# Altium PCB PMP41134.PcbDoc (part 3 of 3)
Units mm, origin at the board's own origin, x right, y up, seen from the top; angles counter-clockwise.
Board outline 252.04 x 132.61 mm, 6 copper layers (Top Layer, Layer 1, Layer 2, Layer 3, Layer 4, Bottom Layer), stack 2.208 mm thick; 221 components, 92 nets, 680 pads, 1197 vias.
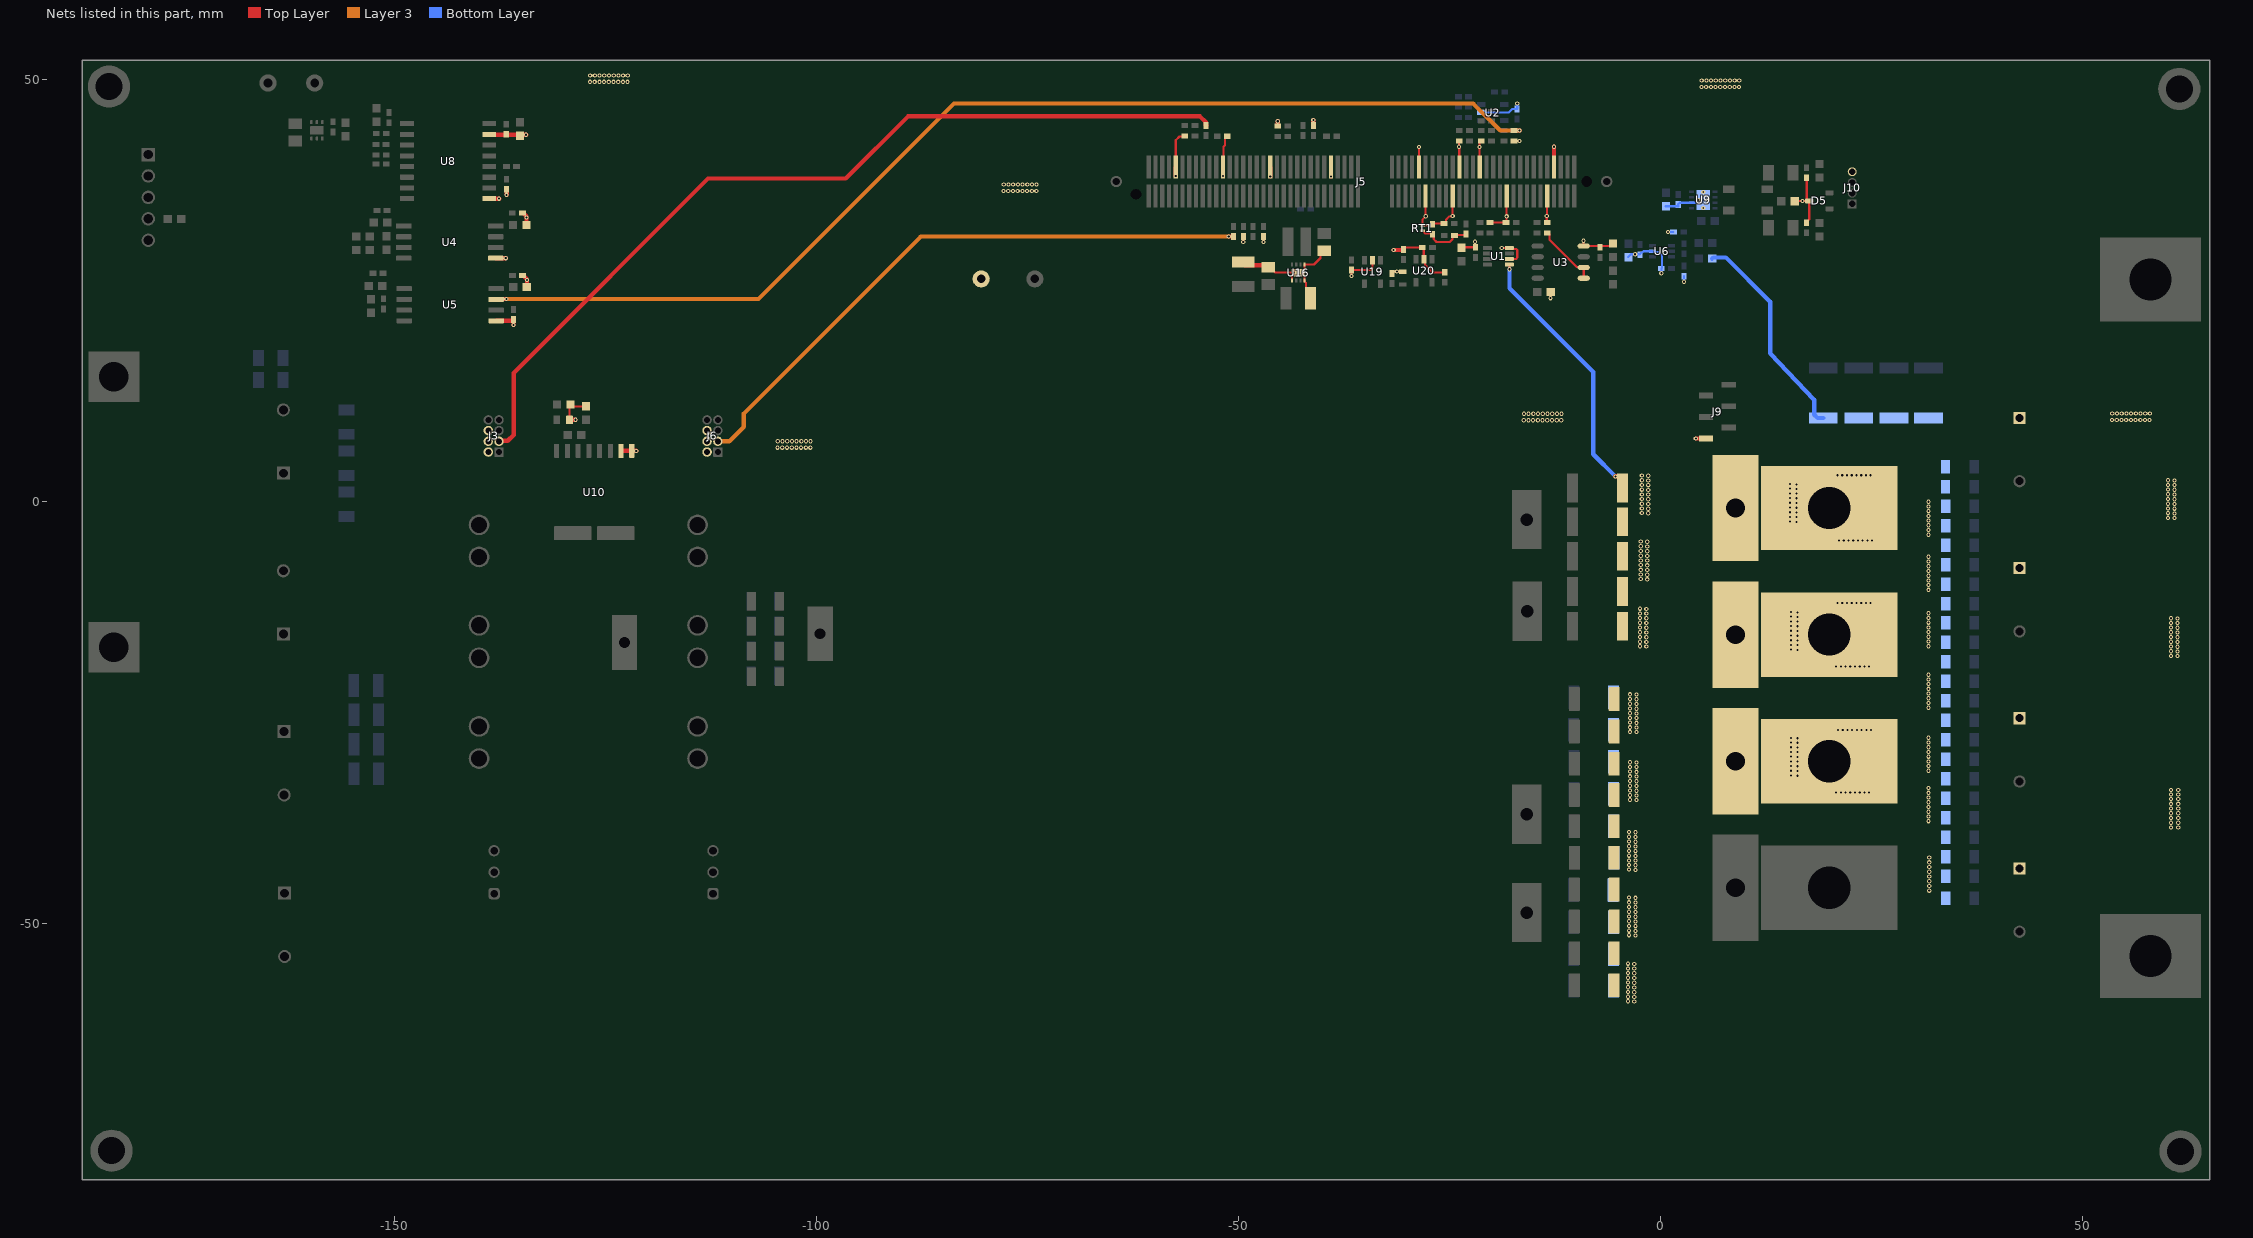
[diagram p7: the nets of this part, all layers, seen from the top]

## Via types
v1: diameter 0.5, hole 0.254, Top Layer to Bottom Layer, tented both sides, 1189 vias
v2: diameter 0.5, hole 0.2, Top Layer to Bottom Layer, 8 vias

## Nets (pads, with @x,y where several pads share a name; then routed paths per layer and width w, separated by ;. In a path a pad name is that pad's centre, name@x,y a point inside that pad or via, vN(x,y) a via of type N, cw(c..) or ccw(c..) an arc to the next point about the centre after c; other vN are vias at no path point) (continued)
SEC_SW1: pad.2@8.839,-15.723 pad.2@19.94,-15.723 R1.2 R2.2 R4.2 R7.2 R16.2 U1.1 | length 32.3
  Top Layer w0.254: U1.1@-17.957,28.113 -17.938,28.094 v1(-17.938,27.567)
  Top Layer w0.508: v1(-5.396,3.023) -4.964,3.023 -4.568,2.627 R1.2@-4.568,1.65
  Bottom Layer w0.508: v1(-17.938,27.567) -17.938,25.304 -8.018,15.384 -8.018,5.645 v1(-5.396,3.023)
  other v1: 20.759,-19.492 21.318,-19.492 21.877,-19.492 22.436,-19.492 22.995,-19.492 23.554,-19.492 24.113,-19.492 24.672,-19.492 16.185,-17.531 15.423,-17.506 -1.727,-17.127 -2.489,-17.094 16.185,-16.972 15.423,-16.947 -1.727,-16.586 -2.489,-16.561 16.185,-16.413 15.423,-16.388 -1.727,-16.027 -2.489,-16.002 16.185,-15.855 15.423,-15.829 -1.727,-15.469 -2.489,-15.443 16.185,-15.296 15.423,-15.27 -1.727,-14.91 -2.489,-14.884 16.185,-14.737 15.423,-14.712 -1.727,-14.351 -2.489,-14.326 16.185,-14.178 15.423,-14.153 -1.727,-13.792 -2.489,-13.767 16.185,-13.619 15.423,-13.594 -1.727,-13.233 -2.489,-13.208 16.185,-13.086 15.423,-13.053 -1.727,-12.675 -2.489,-12.649 20.931,-11.963 21.49,-11.963 22.049,-11.963 22.608,-11.963 23.167,-11.963 23.726,-11.963 24.285,-11.963 24.844,-11.963 -1.626,-9.177 -2.388,-9.144 -1.626,-8.636 -2.388,-8.611 -1.626,-8.077 -2.388,-8.052 -1.626,-7.518 -2.388,-7.493 -1.626,-6.96 -2.388,-6.934 -1.626,-6.401 -2.388,-6.375 -1.626,-5.842 -2.388,-5.817 -1.626,-5.283 -2.388,-5.258 -1.626,-4.724 -2.388,-4.699 -1.499,-1.353 -2.261,-1.321 -1.499,-0.813 -2.261,-0.787 -1.499,-0.254 -2.261,-0.229 -1.499,0.305 -2.261,0.33 -1.499,0.864 -2.261,0.889 -1.499,1.422 -2.261,1.448 -1.499,1.981 -2.261,2.007 -1.499,2.54 -2.261,2.565 -1.499,3.099 -2.261,3.124
SEC_SW2: C5.2 C6.2 C9.2 C10.2 C15.2 C16.2 C19.2 C21.2 C23.2 C27.2 C29.2 C36.2 C37.2 C39.2 C41.2 C43.2 C44.2 C45.2 C46.2 C113.2 pad.2@8.839,-30.723 pad.2@19.94,-30.723
  other v1: -3.15,-59.182 -3.912,-59.149 -3.15,-58.641 -3.912,-58.616 -3.15,-58.082 -3.912,-58.057 -3.15,-57.524 -3.912,-57.498 -3.15,-56.965 -3.912,-56.939 -3.15,-56.406 -3.912,-56.381 -3.15,-55.847 -3.912,-55.822 -3.15,-55.288 -3.912,-55.263 -3.15,-54.73 -3.912,-54.704 -3.023,-51.359 -3.785,-51.326 -3.023,-50.818 -3.785,-50.793 -3.023,-50.259 -3.785,-50.234 -3.023,-49.7 -3.785,-49.675 -3.023,-49.142 -3.785,-49.116 -3.023,-48.583 -3.785,-48.557 -3.023,-48.024 -3.785,-47.999 -3.023,-47.465 -3.785,-47.44 -3.023,-46.906 -3.785,-46.881 -3.023,-43.594 -3.785,-43.561 -3.023,-43.053 -3.785,-43.028 -3.023,-42.494 -3.785,-42.469 -3.023,-41.935 -3.785,-41.91 -3.023,-41.377 -3.785,-41.351 -3.023,-40.818 -3.785,-40.792 -3.023,-40.259 -3.785,-40.234 -3.023,-39.7 -3.785,-39.675 -3.023,-39.141 -3.785,-39.116 -2.906,-35.313 -3.668,-35.281 -2.906,-34.773 -3.668,-34.747 20.759,-34.445 21.318,-34.445 21.877,-34.445 22.436,-34.445 22.995,-34.445 23.554,-34.445 24.113,-34.445 24.672,-34.445 -2.906,-34.214 -3.668,-34.188 -2.906,-33.655 -3.668,-33.63 -2.906,-33.096 -3.668,-33.071 -2.906,-32.537 -3.668,-32.512 16.185,-32.443 15.423,-32.417 -2.906,-31.979 -3.668,-31.953 16.185,-31.884 15.423,-31.858 -2.906,-31.42 -3.668,-31.394 16.185,-31.325 15.423,-31.3 -2.906,-30.861 -3.668,-30.836 16.185,-30.766 15.423,-30.741 16.185,-30.207 15.423,-30.182 16.185,-29.649 15.423,-29.623 16.185,-29.09 15.423,-29.064 16.185,-28.531 15.423,-28.506 16.185,-27.998 15.423,-27.965 -2.906,-27.275 -3.668,-27.243 20.982,-27.01 21.541,-27.01 22.1,-27.01 22.659,-27.01 23.218,-27.01 23.777,-27.01 24.336,-27.01 24.895,-27.01 -2.906,-26.735 -3.668,-26.709 -2.906,-26.176 -3.668,-26.15 -2.906,-25.617 -3.668,-25.592 -2.906,-25.058 -3.668,-25.033 -2.906,-24.499 -3.668,-24.474 -2.906,-23.941 -3.668,-23.915 -2.906,-23.382 -3.668,-23.356 -2.906,-22.823 -3.668,-22.798
SGND: 2.1 C3.2 C18.2 C20.2 C24.2 C26.2 C32.2 C33.2 C34.2 C38.2 C48.2 C49.2 C50.2 C51.2 C52.2 C53.2 C54.2 C55.2 C56.2 C57.2 C58.2 C59.1 C60.2 C61.1 C62.1 C63.1 C64.2 C65.2 C66.2 C67.2 C68.2 C69.2 C70.2 C71.2 C72.2 C74.1 C78.1 C79.2 C80.2 C81.2 C82.2 C83.2 C84.2 C85.2 C87.1 C88.2 C89.2 C92.1 C93.1 C94.2 C95.2 C97.2 C98.2 C99.2 C100.2 C102.2 C103.1 C104.1 C107.2 C108.1 C110.2 C111.2 C112.2 C114.2 C115.2 C116.2 C128.1 C129.1 C130.2 C131.2 C140.1 C142.2 C143.2 C144.2 C149.2 C150.2 C151.2 D5.3 J3.2 J3.4 J3.6 J5.7 J5.10 J5.22 J5.29 J5.35 J5.38 J5.46 J5.47 J5.65 J5.83 J5.97 J5.111 J6.2 J6.4 J6.6 J9.6 J10.4 pad.2@8.839,-0.723 pad.2@19.94,-0.723 R5.1 R6.1 R46.1 R49.1 R50.1 R54.1 R70.1 RT1.1 U1.2 U1.4 U2.2 U3.4 U4.5 U5.5 U6.2 U8.9 U8.15 U9.2 U9.9@5.027,35.764 U10.3 U10.4 U16.1 U16.4 U16.5 U16.9@-42.949,27.169 U19.2 U20.2 | length 158
  Top Layer w0.254: C111.2@-129.293,9.718 -129.293,11.397 C26.2@-129.172,11.518 -128.969,11.316 R6.1@-127.33,11.316 ; J5.111@-57.471,39.648 -57.471,42.837 -57.031,43.277 -56.452,43.277 C89.2@-56.399,43.33 ; J5.97@-51.871,39.648 -51.812,39.706 -51.812,42.059 -51.642,42.229 -51.642,43.145 -51.394,43.393 -51.344,43.393 C88.2@-51.307,43.355 ; C88.2@-51.369,43.318 C88.2@-51.294,43.392 ; v1(-49.471,30.784) C85.2@-49.471,31.434 ; v1(-47.071,30.784) C84.2@-47.071,31.434 ; C130.2@-46.522,27.847 -46.357,27.847 -45.679,27.169 v2(-43.499,27.169) -43.499,26.969 -43.697,26.771 -43.697,26.221 U16.1@-43.699,26.219 ; C128.1@-41.525,24.113 -42.048,24.636 -42.048,25.947 -42.199,26.098 U16.4@-42.199,26.219 -42.201,26.221 -42.201,26.771 -42.399,26.969 v2(-42.399,27.169) -42.399,27.369 -42.201,27.567 -42.201,28.117 U16.5@-42.199,28.119 -41.103,28.119 -40.325,28.896 -40.325,29.323 C131.2@-39.885,29.763 ; v1(-36.652,26.772) -36.662,26.781 -36.662,27.46 C144.2@-36.671,27.469 -34.412,27.469 -34.178,27.704 U19.2@-34.178,28.614 ; C143.2@-31.834,27.069 -31.834,27.13 -31.661,27.303 v1(-31.284,27.303) C142.2@-30.58,27.303 ; C149.2@-30.551,29.832 C149.2@-30.473,29.91 -30.473,29.965 -30.3,30.138 C151.2@-28.271,30.138 -28.259,30.138 -28.086,29.965 U20.2@-28.086,28.748 -27.935,28.597 -27.935,28.098 -27.007,27.17 -26.161,27.17 -26.16,27.169 -25.655,27.169 C150.2@-25.61,27.213 ; J5.47@-28.671,39.648 v1(-28.671,42.052) ; RT1.1@-28.255,32.771 -28.255,32.811 -28.263,32.819 -28.263,33.441 v1(-27.864,33.841) ; RT1.1@-28.225,32.771 -27.203,32.771 C97.2@-27.071,32.902 C97.2@-27.071,33.002 ; v1@-27.871,33.848 -27.867,33.851 -27.867,36.244 J5.46@-27.871,36.248 ; C97.2@-27.007,32.966 -25.611,32.966 -25.438,33.139 -25.438,33.444 -25.054,33.828 -24.718,33.828 v1(-24.671,33.875) J5.38@-24.671,36.248 ; C78.1@-23.883,42.754 -23.917,42.721 v1(-23.917,42.075) -23.894,42.052 -23.894,39.67 J5.35@-23.871,39.648 ; C20.2@-23.442,30.063 -23.344,30.16 -22.011,30.16 v1(-22.011,30.81) ; J5.29@-21.471,39.648 -21.475,39.652 -21.475,42.047 v1(-21.48,42.052) -21.48,42.581 -21.307,42.754 C79.2@-21.283,42.754 ; C81.2@-20.245,33.098 C80.2@-18.346,33.098 -18.271,33.173 J5.22@-18.271,36.248 ; v1(-18.857,30.063) U1.4@-17.957,30.063 -17.859,29.965 -17.174,29.965 -17.026,29.816 -17.026,28.931 -17.174,28.782 -17.938,28.782 U1.2@-17.957,28.763 ; C110.2@-17.397,42.754 v1(-16.747,42.754) ; J5.10@-13.471,36.248 -13.495,36.224 -13.495,33.899 v1(-13.519,33.875) -13.519,33.148 C112.2@-13.469,33.098 ; v1(-13.081,24.133) -13.081,24.839 C3.2@-13.062,24.858 ; v1(-9.171,30.935) -9.171,30.331 U3.4@-9.146,30.306 -5.951,30.306 R5.1@-5.649,30.608 ; C104.1@15.86,35.615 15.907,35.662 D5.3@17.442,35.662 ; C107.2@17.271,33.081 17.271,33.181 17.571,33.481 D5.3@17.571,35.662 D5.3@17.442,35.662 ; C108.1@17.271,38.391 17.271,35.833 D5.3@17.442,35.662
  Top Layer w0.508: U8.9@-138.802,35.921 v1(-137.631,35.921) ; U8.15@-138.802,43.541 -138.756,43.495 -135.3,43.495 C87.1@-135.157,43.351 -135.013,43.495 v1(-134.432,43.495) ; U4.5@-138.028,28.871 v1(-136.849,28.871) ; U5.5@-137.979,21.454 -135.987,21.454 -135.936,21.505 C74.1@-135.936,21.605 v1(-135.936,20.955) ; v1(-136.742,36.374) C94.2@-136.742,37.024 ; C33.2@-134.873,34.226 -134.773,34.226 -134.385,33.838 C32.2@-134.385,32.798 ; C38.2@-134.859,26.796 -134.759,26.796 -134.336,26.373 -134.336,25.5 C48.2@-134.404,25.432 ; C111.2@-129.293,9.718 -129.288,9.723 -128.58,9.723 v1(-128.575,9.728) ; U10.4@-123.19,6.043 v1(-121.387,6.043) ; J5.111@-57.471,39.648 -57.467,39.644 v1(-57.467,38.595) ; J5.97@-51.871,39.648 -51.867,39.644 v1(-51.867,38.608) ; C129.1@-49.471,28.222 -49.284,28.034 -46.71,28.034 C130.2@-46.522,27.847 ; v1(-46.275,38.557) -46.275,39.644 J5.83@-46.271,39.648 ; C83.2@-45.395,44.543 v1(-45.395,45.093) ; C82.2@-41.175,44.593 v1(-41.175,45.243) ; v1(-39.071,38.557) J5.65@-39.071,39.648 ; v1(-31.661,29.832) C149.2@-30.551,29.832 ; J5.7@-12.671,39.648 v1(-12.671,42.075) ; v1(4.14,7.518) 5.313,7.518 J9.6@5.339,7.492
  Bottom Layer w0.254: U2.2@-21.296,46.128 -18.033,46.128 -17.61,46.55 C34.2@-17.026,46.55 v1(-17.026,47.2) ; C93.1@-3.866,29.005 -3.534,29.337 v1(-3.048,29.337) ; v1@-2.998,29.287 -2.948,29.337 -2.514,29.337 C92.1@-2.464,29.287 -2.464,29.387 -2.291,29.56 -2.191,29.56 -2.059,29.692 U6.2@-1.009,29.692 -0.936,29.619 -0.284,29.619 0.116,29.219 0.116,27.702 C98.2@0.053,27.639 v1(0.053,27.089) ; C102.2@0.58,35.015 2.053,35.015 2.053,35.266 2.226,35.439 U9.2@3.627,35.439 4.702,35.439 U9.9@5.027,35.764 ; v1(0.853,31.962) C99.2@1.503,31.962 ; v1(2.738,26.08) C100.2@2.738,26.73
  Bottom Layer w0.508: R70.1@6.062,28.817 6.201,28.956 7.696,28.956 12.954,23.698 12.954,17.602 18.168,12.084 18.168,10.332 18.564,9.936 R46.1@19.218,9.936
  other v1: 31.798,-46.057 31.798,-45.498 31.798,-44.939 31.798,-44.38 31.798,-43.821 31.798,-43.262 31.798,-42.703 31.798,-42.144 60.412,-38.565 61.283,-38.565 60.412,-38.007 61.283,-38.007 31.696,-37.821 60.412,-37.448 61.283,-37.448 31.696,-37.262 60.412,-36.889 61.283,-36.889 31.696,-36.703 60.412,-36.33 61.283,-36.33 31.696,-36.144 60.412,-35.771 61.283,-35.771 31.696,-35.585 60.412,-35.213 61.283,-35.213 31.696,-35.026 60.412,-34.654 61.283,-34.654 31.696,-34.467 60.412,-34.12 61.283,-34.12 31.696,-33.908 31.696,-31.858 31.696,-31.299 31.696,-30.74 31.696,-30.181 31.696,-29.622 31.696,-29.063 31.696,-28.504 31.696,-27.945 31.696,-24.383 31.696,-23.824 31.696,-23.265 31.696,-22.706 31.696,-22.147 31.696,-21.588 31.696,-21.029 31.696,-20.47 61.181,-18.271 60.419,-18.245 61.181,-17.712 60.419,-17.687 61.181,-17.153 60.419,-17.128 31.696,-17.101 61.181,-16.594 60.419,-16.569 31.696,-16.542 61.181,-16.036 60.419,-16.01 31.696,-15.983 61.181,-15.477 60.419,-15.451 31.696,-15.424 61.181,-14.918 60.419,-14.893 31.696,-14.865 61.181,-14.359 60.419,-14.334 31.696,-14.306 61.181,-13.826 60.419,-13.793 31.696,-13.747 31.696,-13.188 31.696,-10.42 31.696,-9.861 31.696,-9.302 31.696,-8.743 31.696,-8.184 31.696,-7.625 31.696,-7.066 31.696,-6.507 21.103,-4.565 21.662,-4.565 22.221,-4.565 22.78,-4.565 23.339,-4.565 23.898,-4.565 24.457,-4.565 25.016,-4.565 31.696,-3.893 31.696,-3.334 31.696,-2.775 16.058,-2.369 15.296,-2.344 31.696,-2.216 60.843,-1.921 60.081,-1.896 16.058,-1.81 15.296,-1.785 31.696,-1.657 60.843,-1.362 60.081,-1.337 16.058,-1.251 15.296,-1.226 31.696,-1.098 60.843,-0.804 60.081,-0.778 16.058,-0.693 15.296,-0.667 31.696,-0.539 60.843,-0.245 60.081,-0.219 16.058,-0.134 15.296,-0.108 31.696,0.02 60.843,0.314 60.081,0.339 16.058,0.425 15.296,0.45 60.843,0.873 60.081,0.898 16.058,0.984 15.296,1.009 60.843,1.432 60.081,1.457 16.058,1.543 15.296,1.568 60.843,1.99 60.081,2.016 16.058,2.076 15.296,2.109 60.843,2.524 60.081,2.556 20.931,3.149 21.49,3.149 22.049,3.149 22.608,3.149 23.167,3.149 23.726,3.149 24.285,3.149 24.844,3.149 -104.647,6.426 -104.088,6.426 -103.529,6.426 -102.97,6.426 -102.412,6.426 -101.853,6.426 -101.294,6.426 -100.761,6.426 -104.621,7.188 -104.063,7.188 -103.504,7.188 -102.945,7.188 -102.386,7.188 -101.827,7.188 -101.269,7.188 -100.728,7.188 -16.256,9.677 -15.697,9.677 -15.138,9.677 -14.58,9.677 -14.021,9.677 -13.462,9.677 -12.903,9.677 -12.344,9.677 -11.811,9.677 53.442,9.703 54,9.703 54.559,9.703 55.118,9.703 55.677,9.703 56.236,9.703 56.794,9.703 57.353,9.703 57.887,9.703 -16.231,10.439 -15.672,10.439 -15.113,10.439 -14.554,10.439 -13.995,10.439 -13.437,10.439 -12.878,10.439 -12.319,10.439 -11.778,10.439 53.467,10.465 54.026,10.465 54.585,10.465 55.143,10.465 55.702,10.465 56.261,10.465 56.82,10.465 57.379,10.465 57.919,10.465 -134.336,26.275 -134.385,33.676 -18.271,33.828 16.762,35.63 -77.876,36.83 -77.318,36.83 -76.759,36.83 -76.2,36.83 -75.641,36.83 -75.082,36.83 -74.524,36.83 -73.99,36.83 -77.851,37.592 -77.292,37.592 -76.733,37.592 -76.175,37.592 -75.616,37.592 -75.057,37.592 -74.498,37.592 -73.958,37.592 4.801,49.149 5.359,49.149 5.918,49.149 6.477,49.149 7.036,49.149 7.595,49.149 8.153,49.149 8.712,49.149 9.246,49.149 -126.873,49.759 -126.314,49.759 -125.755,49.759 -125.197,49.759 -124.638,49.759 -124.079,49.759 -123.52,49.759 -122.961,49.759 -122.428,49.759 4.826,49.911 5.385,49.911 5.944,49.911 6.502,49.911 7.061,49.911 7.62,49.911 8.179,49.911 8.738,49.911 9.278,49.911 -126.848,50.521 -126.289,50.521 -125.73,50.521 -125.171,50.521 -124.612,50.521 -124.054,50.521 -123.495,50.521 -122.936,50.521 -122.395,50.521
  other v2: 5.027,34.814 4.477,35.764 5.577,35.764 5.027,36.714
TMP_SEC: C97.1 R67.2 R89.1 RT1.2 | length 6.6
  Top Layer w0.254: RT1.2@-28.255,32.121 -28.13,32.121 -28.082,32.073 -28.082,31.951 -27.933,31.802 -27.171,31.802 -26.914,31.546 -26.914,31.128 -26.582,30.797 -25.011,30.797 -24.694,31.113 -24.694,31.433 -24.521,31.606 -24.457,31.606 -23.211,31.606 R89.1@-23.086,31.731
Top_ZVD1: J3.3 R101.1 | length 104.7
  Top Layer w0.508: J3.3@-137.643,7.188 -137.595,7.235 -136.605,7.235 -135.906,7.934 -135.906,15.274 -112.878,38.303 -96.571,38.303 -89.205,45.669 -54.597,45.669 -53.919,44.991 -53.919,44.639 R101.1@-53.873,44.593
Top_ZVD2: J6.3 R98.1 | length 72
  Top Layer w0.508: v1(-51.198,31.434) R98.1@-50.648,31.434
  Layer 3 w0.508: J6.3@-111.721,7.188 -110.352,7.188 -108.636,8.905 -108.636,10.465 -87.666,31.434 v1(-51.198,31.434)
VSNS_PRI: R85.2 U5.7 | length 132.8
  Top Layer w0.508: U5.7@-137.979,23.994 -137.945,24.028 v1(-136.774,24.028) ; R85.2@-17.397,43.989 v1(-16.747,43.989)
  Layer 3 w0.508: v1(-136.774,24.028) -106.909,24.028 -83.737,47.2 -22.244,47.2 -19.033,43.989 v1(-16.747,43.989)
VSNS_SEC: R22.2 U3.1 U3.2 | length 7.7
  Top Layer w0.254: R22.2@-13.469,31.851 -13.369,31.851 -13.196,31.678 -13.196,31.043 -9.973,27.82 -9.199,27.82 U3.2@-9.146,27.766 U3.1@-9.146,26.496
pads on no net: J5.1 J5.2 J5.3 J5.4 J5.5 J5.6 J5.8 J5.9 J5.11 J5.12 J5.13 J5.15 J5.16 J5.17 J5.18 J5.19 J5.21 J5.24 J5.26 J5.27 J5.28 J5.32 J5.33 J5.36 J5.37 J5.39 J5.40 J5.41 J5.42 J5.43 J5.44 J5.45 J5.57 J5.58 J5.59 J5.60 J5.61 J5.62 J5.63 J5.64 J5.66 J5.67 J5.74 J5.76 J5.77 J5.78 J5.79 J5.80 J5.81 J5.82 J5.85 J5.87 J5.89 J5.90 J5.91 J5.92 J5.93 J5.94 J5.95 J5.96 J5.99 J5.100 J5.101 J5.102 J5.104 J5.106 J5.107 J5.108 J5.109 J5.110 J5.113 J5.114 J5.115 J5.116 J5.117 J5.118 J5.119 J5.120 J5.181 J5.182 J5.185 J5.186 J7.1 J8.1 J10.3 R26.1 R30.2 R34.1 R74.1 RT1.1S RT1.2S U3.5 U3.6 U3.7 U8.6 U8.7 U8.10 U8.11 U9.5 U9.9@5.027,35.129 U9.9@5.027,36.399 U10.5 U16.8 U16.9@-42.499,27.169 U16.9@-43.399,27.169 U19.4

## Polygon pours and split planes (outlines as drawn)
HV_SW2 on Bottom Layer "BOTTOM_LAYER_HV_SW2_P091" (solid, remove dead copper, pour order 91): -111.347,-11.869 -109.29,-9.812 -107.358,-9.812 -107.096,-10.074 -107.096,-11.869
RTN on Bottom Layer "BOTTOM_LAYER_RTN_P079" (solid, remove dead copper, pour order 79): -186.817,17.712 -186.043,18.486 -165.886,18.486 -165.352,17.952 -165.352,13.464 -166.118,12.956 -175.244,7.214 -185.649,7.214 -186.817,8.382
48Vo- on Bottom Layer "BOTTOM_LAYER_48VO-_P077" (solid, remove dead copper, pour order 77): 33.68,15.088 62.433,15.088 64.008,16.662 64.008,34.163 62.23,35.941 30.173,35.941 16.879,22.648 16.879,15.785 17.577,15.088
48Vo+ on Bottom Layer "BOTTOM_LAYER_48VO+_P075" (solid, remove dead copper, pour order 75): 45.35,-47.964 63.661,-47.964 63.932,-48.235 63.932,-68.732 62.56,-70.104 46.177,-70.104 44.755,-68.682 44.755,-48.569
48Vo+ on Bottom Layer "BOTTOM_LAYER_48VO+_P033" (solid, remove dead copper, pour order 33): 36.986,6.198 43.028,6.198 44.145,5.08 44.185,-3.491 40.386,-5.557 40.386,-9.866 44.182,-12.37 44.146,-21.49 40.107,-24.069 40.107,-28.08 43.869,-30.723 43.869,-39.464 40.107,-41.618 40.107,-45.072 43.869,-47.964 43.869,-68.551 42.24,-70.18 36.246,-70.18 36.246,5.458
48Vo+ on Bottom Layer "BOTTOM_LAYER_48VO+_P036" (solid, remove dead copper, pour order 36): 5.47,-39.716 5.994,-39.192 14.351,-39.192 28.016,-39.192 28.575,-39.751 28.575,-47.276 30.702,-49.403 35.491,-49.403 38.053,-46.841 38.71,-47.498 38.71,-70.18 14.097,-70.18 5.47,-61.554
SGND on Bottom Layer "BOTTOM_LAYER_SGND_P034" (solid, remove dead copper, pour order 34): 16.725,9.157 18.567,7.315 43.663,7.315 45.187,5.791 45.187,-4.242 41.631,-6.214 41.631,-9.093 45.491,-11.963 45.491,-22.018 41.25,-24.961 41.25,-27.305 45.034,-30.124 45.034,-39.962 41.427,-42.329 41.427,-44.554 43.805,-46.431 62.154,-46.431 63.881,-44.704 63.881,10.135 60.884,13.132 18.821,13.132 16.725,11.036
48Vo- on Bottom Layer "BOTTOM_LAYER_48VO-_P040" (solid, remove dead copper, pour order 40): 17.526,19.152 33.147,19.152 33.998,18.301 33.998,15.405 33.68,15.088 17.577,15.088 17.018,15.646 17.018,18.644
3.3Vs on Bottom Layer "BOTTOM_LAYER_3.3VS_P039" (solid, remove dead copper, pour order 39): -33.082,24.384 -32.309,26.187 -30.127,26.187 -29.667,25.727 -29.667,22.885 -30.709,21.844 -133.147,21.844 -137.312,26.01 -137.312,45.263 -136.855,45.72 -133.909,45.72 -133.655,45.466 -133.655,27.381 -130.658,24.384
SEC_SW1 on Bottom Layer "BOTTOM_LAYER_SEC_SW1_P038" (solid, remove dead copper, pour order 38): 12.422,-9.019 28.258,-9.019 28.651,-9.412 28.651,-22.073 28.194,-22.53 11.855,-22.53 11.855,-9.585
SEC_SW2 on Bottom Layer "BOTTOM_LAYER_SEC_SW2_P037" (solid, remove dead copper, pour order 37): 11.527,-24.105 27.822,-24.105 28.575,-24.857 28.575,-36.703 27.813,-37.465 11.527,-37.465
SGND on Bottom Layer "BOTTOM_LAYER_SGND_P035" (solid, remove dead copper, pour order 35): 4.751,5.749 5.149,6.147 11.836,6.147 16.725,11.036 27.877,11.036 37.694,8.56 34.535,5.937 34.611,-47.778 34.326,-48.064 31.096,-48.064 29.921,-46.888 29.921,-8.356 28.652,-7.087 12.408,-7.087 5.994,-7.087 4.751,-5.844
NetR1_1 on Bottom Layer "BOTTOM_LAYER_NETR1_1_P032" (solid, remove dead copper, pour order 32): -20.549,3.123 -19.751,3.921 -9.737,3.921 -9.144,3.327 -9.144,-18.034 -9.728,-18.618 -19.761,-18.618 -20.549,-17.831
SEC_SW1 on Bottom Layer "BOTTOM_LAYER_SEC_SW1_P031" (solid, remove dead copper, pour order 31): -5.618,3.475 -5.173,3.921 1.566,3.921 2.464,3.023 2.464,-6.731 4.751,-9.019 12.422,-9.019 13.056,-9.652 13.056,-21.946 12.471,-22.53 0.102,-22.53 -5.618,-16.81
SEC_SW2 on Bottom Layer "BOTTOM_LAYER_SEC_SW2_P030" (solid, remove dead copper, pour order 30): -6.334,-21.082 -3.48,-21.082 -0.492,-24.069 11.82,-24.069 12.548,-24.797 12.548,-37.109 12.192,-37.465 4.75,-37.465 3.759,-38.456 3.759,-60.325 2.642,-61.443 -5.893,-61.443 -6.655,-60.681 -6.655,-21.415
NetC5_1 on Bottom Layer "BOTTOM_LAYER_NETC5_1_P029" (solid, remove dead copper, pour order 29): -20.879,-21.895 -19.812,-20.828 -9.622,-20.828 -9.144,-21.306 -9.144,-60.452 -10.185,-61.493 -19.558,-61.493 -20.879,-60.173
NetC1_2 on Bottom Layer "BOTTOM_LAYER_NETC1_2_P015" (solid, remove dead copper, pour order 15): -105.131,-10.312 -104.242,-9.423 -97.03,-9.423 -96.241,-10.213 -96.241,-21.717 -96.723,-22.2 -104.724,-22.2 -105.131,-21.793
HV_SW2 on Bottom Layer "BOTTOM_LAYER_HV_SW2_P014" (solid, remove dead copper, pour order 14): -116.314,-11.996 -115.373,-11.055 -107.755,-11.055 -107.096,-11.714 -107.096,-21.69 -107.308,-21.902 -115.831,-21.902 -116.314,-21.419
HVBUS on Bottom Layer "BOTTOM_LAYER_HVBUS_P009" (solid, remove dead copper, pour order 9): -136.931,-0.787 -111.607,-0.787 -110.719,-1.675 -110.719,-7.722 -111.481,-8.484 -137.643,-8.484 -137.643,-1.473 -137.427,-1.257
PGND on Bottom Layer "BOTTOM_LAYER_PGND_P007" (solid, remove dead copper, pour order 7): -136.5,-24.638 -110.719,-24.638 -110.185,-25.171 -110.16,-25.171 -110.16,-34.239 -111.074,-35.154 -140.589,-35.154 -140.589,-28.727
PGND on Bottom Layer "BOTTOM_LAYER_PGND_P002" (solid, remove dead copper, pour order 2): -163.92,13.614 -163.92,18.734 -163.752,18.872 -161.199,18.872 -160.426,18.099 -160.426,10.15 -167.767,4.977 -167.767,-48.717 -165.71,-50.775 -159.69,-50.775 -157.353,-53.111 -157.353,-60.376 -158.217,-61.239 -174.219,-61.239 -176.276,-59.182 -176.276,5.309
PGND on Bottom Layer "BOTTOM_LAYER_PGND_P004" (solid, remove dead copper, pour order 4): -152.641,-32.703 -152.641,-37.752 -159.01,-44.121 -159.01,-49.79 -161.608,-52.388 -161.608,-61.239 -145.068,-61.239 -142.443,-58.615 -142.443,-25.116
PGND on Bottom Layer "BOTTOM_LAYER_PGND_P003" (solid, remove dead copper, pour order 3): -152.641,-20.413 -149.411,-20.413 -145.186,-24.638 -136.5,-24.638 -136.144,-24.994 -136.144,-33.066 -142.727,-39.649 -146.545,-39.649 -152.641,-33.553
HVBUS on Bottom Layer "BOTTOM_LAYER_HVBUS_P001" (solid, remove dead copper, pour order 1): -164.948,-14.619 -150.368,-0.787 -136.931,-0.787 -136.373,-1.346 -136.373,-7.772 -136.754,-8.153 -137.084,-8.484 -143.866,-8.484 -154.211,-18.829 -154.211,-21.388 -164.948,-21.388
HVBUS on Bottom Layer "BOTTOM_LAYER_HVBUS_P000" (solid, remove dead copper, pour order 0): -164.948,-15.367 -163.881,-14.3 -154.686,-14.3 -154.203,-14.783 -154.211,-14.79 -154.211,-33.586 -154.661,-34.036 -158.623,-34.036 -164.948,-28.963
HV_SW2 on Top Layer "TOP_LAYER_HV_SW2_P090" (solid, remove dead copper, pour order 90): -110.312,-10.465 -109.499,-9.652 -107.518,-9.652 -107.096,-10.074 -107.096,-12.536 -107.517,-12.957 -107.876,-12.598 -111.532,-12.598 -111.532,-11.684
48Vo+ on Top Layer "TOP_LAYER_48VO+_P088" (solid, remove dead copper, pour order 88): 43.074,4.318 43.758,3.634 43.758,-1.886 40.107,-5.537 40.107,-9.532 44.145,-12.473 44.145,-20.321 40.107,-23.379 40.107,-28.08 43.805,-31.373 43.805,-37.856 40.107,-41.554 40.107,-45.072 43.869,-48.835 43.869,-67.168 41.085,-69.952 13.792,-69.952 5.47,-61.63 5.47,-39.64 5.994,-39.116 6.071,-39.192 28.016,-39.192 28.651,-39.827 28.651,-49.251 29.312,-49.911 35.268,-49.911 35.917,-49.262 36.115,0.775 40.942,4.318
SGND on Top Layer "TOP_LAYER_SGND_P087" (solid, remove dead copper, pour order 87): 38.35,5.749 43.756,5.749 45.187,4.318 45.187,-2.658 41.25,-6.595 41.25,-8.81 45.491,-11.963 45.491,-21.029 41.25,-24.288 41.25,-27.305 45.034,-30.723 45.034,-38.722 41.427,-42.329 41.427,-44.554 43.304,-46.431 47.372,-46.431 50.362,-43.442 62.451,-43.442 63.881,-42.012 63.881,10.135 61.818,12.198 39.938,12.198
SGND on Top Layer "TOP_LAYER_SGND_P086" (solid, remove dead copper, pour order 86): 11.201,5.749 12.175,5.749 17.268,12.198 43.632,12.198 44.704,11.125 44.704,8.612 34.573,1.251 34.573,-47.462 33.972,-48.064 31.096,-48.064 30.023,-46.99 30.023,-8.686 28.296,-6.96 11.862,-6.96 11.303,-6.401
NetT1_1 on Top Layer "TOP_LAYER_NETT1_1_P084" (solid, remove dead copper, pour order 84): -125.628,-20.295 -119.914,-20.295 -119.736,-20.095 -119.736,-3.607 -120.599,-2.743 -126.009,-2.743 -126.136,-2.87 -126.136,-19.787
RTN on Top Layer "TOP_LAYER_RTN_P080" (solid, remove dead copper, pour order 80): -186.043,18.486 -165.886,18.486 -165.352,17.952 -165.352,13.464 -166.118,12.956 -175.284,7.214 -185.562,7.214 -186.56,8.211 -186.56,17.969
48Vo- on Top Layer "TOP_LAYER_48VO-_P078" (solid, remove dead copper, pour order 78): 16.879,22.648 30.173,35.941 62.23,35.941 64.008,34.163 64.008,16.662 62.433,15.088 17.577,15.088 16.879,15.785
48Vo+ on Top Layer "TOP_LAYER_48VO+_P076" (solid, remove dead copper, pour order 76): 51.41,-46.177 51.765,-45.822 63.83,-45.822 63.932,-45.923 63.932,-68.732 62.56,-70.104 52.476,-70.104 51.41,-69.037
SGND on Top Layer "TOP_LAYER_SGND_P053" (solid, remove dead copper, pour order 53): 4.751,4.953 5.547,5.749 28.889,5.749 29.921,4.717 29.921,-6.563 28.763,-7.721 5.741,-7.721 4.751,-6.732
SEC_SW2 on Top Layer "TOP_LAYER_SEC_SW2_P028" (solid, remove dead copper, pour order 28): -6.655,-22.327 -6.655,-21.415 -6.322,-21.082 -3.505,-21.082 -0.483,-24.105 27.823,-24.105 28.575,-24.857 28.575,-36.897 28.007,-37.465 4.75,-37.465 3.759,-38.456 3.759,-60.35 2.667,-61.443 -5.893,-61.443 -6.655,-60.681
NetC5_1 on Top Layer "TOP_LAYER_NETC5_1_P027" (solid, remove dead copper, pour order 27): -20.879,-21.895 -19.812,-20.828 -9.622,-20.828 -9.144,-21.306 -9.144,-60.452 -10.185,-61.493 -19.558,-61.493 -20.879,-60.173
SEC_SW1 on Top Layer "TOP_LAYER_SEC_SW1_P026" (solid, remove dead copper, pour order 26): -5.618,3.475 -5.173,3.921 1.566,3.921 2.464,3.023 2.464,-6.731 4.751,-9.019 27.306,-9.019 28.538,-10.25 28.538,-21.338 27.346,-22.53 0.102,-22.53 -5.618,-16.81
NetR1_1 on Top Layer "TOP_LAYER_NETR1_1_P025" (solid, remove dead copper, pour order 25): -20.549,3.123 -19.751,3.921 -9.737,3.921 -9.144,3.327 -9.144,-18.034 -9.728,-18.618 -19.761,-18.618 -20.549,-17.831
NetC1_2 on Top Layer "TOP_LAYER_NETC1_2_P013" (solid, remove dead copper, pour order 13): -105.131,-10.293 -104.49,-9.652 -96.801,-9.652 -96.241,-10.213 -96.241,-21.717 -96.977,-22.454 -104.394,-22.454 -105.131,-21.717
HV_SW2 on Top Layer "TOP_LAYER_HV_SW2_P012" (solid, remove dead copper, pour order 12): -115.494,-21.971 -107.267,-21.971 -107.096,-21.793 -107.096,-11.446 -107.487,-11.055 -115.475,-11.055 -115.976,-11.556 -115.976,-21.488
HV_SW1 on Top Layer "TOP_LAYER_HV_SW1_P010" (solid, remove dead copper, pour order 10): -141.732,-12.598 -134.49,-12.598 -132.258,-10.269 -132.258,-3.404 -131.653,-2.798 -126.656,-2.798 -126.598,-2.856 -126.598,-17.607 -129.468,-20.477 -141.626,-20.477 -142.291,-19.812 -142.291,-13.157
PGND on Top Layer "TOP_LAYER_PGND_P008" (solid, remove dead copper, pour order 8): -137.427,-24.638 -110.719,-24.638 -110.16,-25.197 -110.16,-34.239 -111.074,-35.154 -140.589,-35.154 -140.589,-24.847
PGND on Top Layer "TOP_LAYER_PGND_P006" (solid, remove dead copper, pour order 6): -164.354,13.322 -161.179,13.322 -160.813,12.956 -160.813,9.878 -167.767,4.977 -167.767,-48.743 -165.557,-50.952 -165.506,-50.902 -160.045,-50.902 -160.045,-50.825 -159.01,-49.79 -159.01,-44.121 -152.641,-37.752 -152.641,-20.413 -149.411,-20.413 -145.186,-24.638 -136.5,-24.638 -136.144,-24.994 -136.144,-33.122 -142.443,-39.421 -142.443,-58.615 -145.068,-61.239 -174.219,-61.239 -176.276,-59.182 -176.276,5.309
HVBUS on Top Layer "TOP_LAYER_HVBUS_P005" (solid, remove dead copper, pour order 5): -164.948,-14.619 -150.368,-0.787 -136.931,-0.787 -136.373,-1.346 -136.373,-7.772 -137.084,-8.484 -143.942,-8.484 -155.143,-19.685 -155.143,-33.553 -155.626,-34.036 -158.623,-34.036 -164.948,-28.963
NetC1_2 on Layer 2 "LAYER_2_NETC1_2_P093" (solid, remove dead copper, pour order 93): -105.131,-10.312 -104.555,-9.737 -96.716,-9.737 -96.241,-10.213 -96.241,-21.717 -96.977,-22.454 -104.47,-22.454 -105.131,-21.793
HV_SW2 on Layer 2 "LAYER_2_HV_SW2_P092" (solid, remove dead copper, pour order 92): -116.314,-10.316 -115.942,-9.944 -107.425,-9.944 -106.941,-10.428 -106.941,-21.946 -107.449,-22.454 -115.716,-22.454 -116.314,-21.856
48Vo+ on Layer 2 "LAYER_2_48VO+_P089" (solid, remove dead copper, pour order 89): 5.98,-39.154 33.147,-39.154 34.273,-38.029 34.273,3.878 36.144,5.749 55.241,5.749 56.642,4.348 56.642,-40.616 49.632,-47.626 49.632,-60.195 47.216,-62.611 6.783,-62.611 5.47,-61.299 5.47,-39.827
SEC_SW1 on Layer 2 "LAYER_2_SEC_SW1_P068" (solid, remove dead copper, pour order 68): -5.695,3.399 -5.173,3.921 1.566,3.921 2.464,3.023 2.464,-6.731 4.751,-9.019 27.864,-9.019 28.538,-9.692 28.538,-22.186 28.194,-22.53 0.102,-22.53 -5.699,-16.73
SEC_SW2 on Layer 2 "LAYER_2_SEC_SW2_P071" (solid, remove dead copper, pour order 71): -6.655,-21.415 -6.322,-21.082 -3.505,-21.082 -0.518,-24.069 27.808,-24.069 28.575,-24.836 28.575,-36.897 28.007,-37.465 4.75,-37.465 3.759,-38.456 3.759,-60.325 2.642,-61.443 -5.893,-61.443 -6.655,-60.681
NetC5_1 on Layer 2 "LAYER_2_NETC5_1_P070" (solid, remove dead copper, pour order 70): -20.879,-21.895 -19.812,-20.828 -9.622,-20.828 -9.144,-21.306 -9.144,-60.452 -10.185,-61.493 -19.558,-61.493 -20.879,-60.173
NetR1_1 on Layer 2 "LAYER_2_NETR1_1_P069" (solid, remove dead copper, pour order 69): -20.549,3.123 -19.751,3.921 -9.737,3.921 -9.144,3.327 -9.144,-18.034 -9.728,-18.618 -19.761,-18.618 -20.549,-17.831 -20.549,3.123
HV_SW1 on Layer 2 "LAYER_2_HV_SW1_P067" (solid, remove dead copper, pour order 67): -132.258,-3.404 -131.572,-2.718 -126.737,-2.718 -126.598,-2.856 -126.598,-17.607 -129.468,-20.477 -141.626,-20.477 -142.291,-19.812 -142.291,-13.157 -141.732,-12.598 -134.49,-12.598 -132.258,-10.367
NetT1_1 on Layer 2 "LAYER_2_NETT1_1_P066" (solid, remove dead copper, pour order 66): -126.136,-2.87 -126.031,-2.765 -120.577,-2.765 -119.736,-3.607 -119.736,-19.966 -120.062,-20.293 -125.734,-20.293 -126.136,-19.89
SGND on Layer 2 "LAYER_2_SGND_P055" (solid, remove dead copper, pour order 55): -139.236,4.623 -96.54,4.623 -95.391,5.712 -95.391,20.244 -21.445,20.244 -21.445,7.876 -20.319,6.68 34.822,6.68 39.853,11.711 39.853,50.063 38.049,51.867 -138.659,51.867 -139.903,50.623 -139.903,5.29
SGND on Layer 2 "LAYER_2_SGND_P051" (solid, remove dead copper, pour order 51): 4.751,4.953 5.547,5.749 29.098,5.749 30.226,4.621 30.226,-6.647 29.152,-7.721 5.741,-7.721 4.751,-6.732
12Vp on Layer 2 "LAYER_2_12VP_P021" (solid, remove dead copper, pour order 21): -166.802,51.689 -163.151,51.689 -162.814,51.352 -162.814,47.574 -160.477,45.237 -160.477,42.723 -161.087,42.113 -161.188,42.215 -164.948,42.215 -164.948,43.485 -167.284,45.822 -167.284,51.206
12Vp on Layer 2 "LAYER_2_12VP_P019" (solid, remove dead copper, pour order 19): -114.732,-38.049 -110.439,-38.049 -109.804,-38.684 -109.804,-41.935 -110.315,-42.446 -143.457,-42.446 -148.67,-37.233 -148.67,9.335 -164.948,25.612 -164.948,43.201 -164.608,43.541 -160.879,43.541 -160.477,43.139 -160.477,27.124 -144.636,11.283 -144.636,-35.018 -141.605,-38.049
HVBUS on Layer 4 "LAYER_4_HVBUS_P095" (solid, remove dead copper, pour order 95): -186.817,-13.668 -186.357,-13.208 -155.321,-13.208 -154.229,-14.3 -154.229,-33.604 -154.661,-34.036 -158.623,-34.036 -163.719,-29.947 -186.614,-29.947 -186.817,-29.743
SGND on Layer 4 "LAYER_4_SGND_P044" (solid, remove dead copper, pour order 44): -21.464,20.244 -21.464,7.851 -20.206,6.593 29.647,6.68 32.69,3.637 32.69,-43.924 34.587,-45.822 48.285,-45.822 49.936,-44.171 49.936,48.235 46.304,51.867 -138.659,51.867 -139.903,50.623 -139.903,5.29 -139.236,4.623 -96.578,4.623 -95.391,5.712 -95.391,20.244
NetC5_1 on Layer 4 "LAYER_4_NETC5_1_P064" (solid, remove dead copper, pour order 64): -20.879,-21.895 -19.812,-20.828 -9.622,-20.828 -9.144,-21.306 -9.144,-60.452 -10.185,-61.493 -19.558,-61.493 -20.879,-60.173
NetR1_1 on Layer 4 "LAYER_4_NETR1_1_P063" (solid, remove dead copper, pour order 63): -20.549,3.123 -19.751,3.921 -9.737,3.921 -9.144,3.327 -9.144,-18.034 -9.728,-18.618 -19.761,-18.618 -20.549,-17.831 -20.549,3.123
48Vo+ on Layer 4 "LAYER_4_48VO+_P062" (solid, remove dead copper, pour order 62): 5.47,-39.673 5.951,-39.192 28.81,-39.192 29.921,-40.303 29.921,-61.216 28.552,-62.586 6.541,-62.586 5.47,-61.515
SEC_SW2 on Layer 4 "LAYER_4_SEC_SW2_P061" (solid, remove dead copper, pour order 61): -6.655,-22.276 -6.655,-21.415 -6.322,-21.082 -3.505,-21.082 -0.518,-24.069 28.9,-24.069 29.921,-25.091 29.921,-36.662 29.118,-37.465 4.75,-37.465 3.759,-38.456 3.759,-60.325 2.642,-61.443 -5.893,-61.443 -6.655,-60.681
SEC_SW1 on Layer 4 "LAYER_4_SEC_SW1_P060" (solid, remove dead copper, pour order 60): -5.173,3.921 1.566,3.921 2.464,3.023 2.464,-6.731 4.751,-9.019 28.931,-9.019 29.921,-10.008 29.921,-21.812 29.204,-22.53 0.102,-22.53 -5.623,-16.806 -5.623,3.471
SGND on Layer 4 "LAYER_4_SGND_P052" (solid, remove dead copper, pour order 52): 4.751,4.953 5.547,5.749 28.603,5.749 29.921,4.431 29.921,-6.563 28.763,-7.721 5.741,-7.721 4.751,-6.732
PGND on Layer 4 "LAYER_4_PGND_P023" (solid, remove dead copper, pour order 23): -186.157,42.871 -176.221,51.689 -147.65,51.689 -146.837,50.876 -146.837,16.525 -143.65,12.648 -143.65,-33.084 -138.887,-37.846 -110.388,-37.846 -109.677,-38.557 -109.677,-49.124 -110.947,-50.394 -143.485,-50.394 -149.411,-44.467 -149.411,6.295 -152.451,9.335 -163.919,9.335 -164.744,10.16 -164.744,15.23 -163.449,16.525 -163.449,18.331 -164.219,19.101 -184.556,19.101 -186.157,20.701
48Vo+ on Layer 3 "LAYER_3_48VO+_P074" (solid, remove dead copper, pour order 74): 33.147,3.218 34.323,4.394 62.471,4.394 63.932,2.934 63.932,-68.732 62.56,-70.104 34.468,-70.104 33.147,-68.783
HVBUS on Layer 3 "LAYER_3_HVBUS_P024" (solid, remove dead copper, pour order 24): -150.378,-0.787 -110.738,-0.787 -110.312,-1.213 -110.312,-8.382 -110.744,-8.814 -143.281,-8.814 -154.211,-19.743 -154.211,-33.586 -154.661,-34.036 -158.623,-34.036 -164.948,-28.963 -164.948,-14.619
HVBUS on Layer 1 "LAYER_1_HVBUS_P094" (solid, remove dead copper, pour order 94): -187.274,-13.668 -186.814,-13.208 -156.286,-13.208 -155.143,-14.351 -155.143,-32.384 -155.881,-33.122 -159.925,-33.122 -163.719,-29.947 -186.309,-29.947 -187.274,-28.981
SGND on Layer 1 "LAYER_1_SGND_P058" (solid, remove dead copper, pour order 58): 20.1,5.749 35.111,5.749 40.398,11.036 62.844,11.036 63.932,9.948 63.881,9.897 63.881,-44.044 62.052,-45.872 32.382,-45.872 30.023,-43.513 30.023,-8.433 29.311,-7.721 19.675,-7.721 19.675,5.324
48Vo+ on Layer 1 "LAYER_1_48VO+_P059" (solid, remove dead copper, pour order 59): 5.47,-39.716 5.951,-39.236 5.951,-39.192 28.016,-39.192 28.575,-39.751 28.575,-61.46 27.449,-62.586 6.656,-62.586 5.47,-61.561
SGND on Layer 1 "LAYER_1_SGND_P056" (solid, remove dead copper, pour order 56): -21.464,20.244 -21.464,7.876 -20.319,6.68 34.822,6.68 39.875,11.733 39.875,50.041 38.049,51.867 -138.659,51.867 -139.903,50.623 -139.903,5.29 -139.208,4.596 -96.568,4.596 -95.391,5.747 -95.391,20.244
SGND on Layer 1 "LAYER_1_SGND_P049" (solid, remove dead copper, pour order 49): 4.751,4.953 5.547,5.749 27.983,5.749 29.058,4.675 29.058,-6.681 28.018,-7.721 5.741,-7.721 4.751,-6.732
SEC_SW2 on Layer 1 "LAYER_1_SEC_SW2_P048" (solid, remove dead copper, pour order 48): -6.655,-21.409 -6.328,-21.082 -3.502,-21.082 -0.515,-24.069 27.787,-24.069 28.575,-24.857 28.575,-36.897 28.007,-37.465 4.75,-37.465 3.759,-38.456 3.759,-60.35 2.667,-61.443 -5.893,-61.443 -6.655,-60.681
SEC_SW1 on Layer 1 "LAYER_1_SEC_SW1_P047" (solid, remove dead copper, pour order 47): -5.623,3.25 -5.623,3.471 -5.173,3.921 1.566,3.921 2.464,3.023 2.464,-6.731 4.751,-9.019 27.864,-9.019 28.575,-9.729 28.575,-22.149 28.194,-22.53 0.102,-22.53 -5.618,-16.81 -5.618,3.475
NetC5_1 on Layer 1 "LAYER_1_NETC5_1_P043" (solid, remove dead copper, pour order 43): -20.879,-21.895 -19.812,-20.828 -9.622,-20.828 -9.144,-21.306 -9.144,-60.452 -10.185,-61.493 -19.558,-61.493 -20.879,-60.173
NetR1_1 on Layer 1 "LAYER_1_NETR1_1_P042" (solid, remove dead copper, pour order 42): -20.549,3.123 -19.751,3.921 -9.737,3.921 -9.144,3.327 -9.144,-18.034 -9.728,-18.618 -19.761,-18.618 -20.549,-17.831
PGND on Layer 1 "LAYER_1_PGND_P018" (solid, remove dead copper, pour order 18): -175.896,52.045 -148.006,52.045 -146.837,50.876 -146.837,16.525 -143.65,12.648 -143.65,-33.084 -138.887,-37.846 -110.388,-37.846 -109.677,-38.557 -109.677,-49.124 -110.947,-50.394 -143.485,-50.394 -149.411,-44.467 -149.411,6.862 -161.11,19.05 -184.506,19.05 -186.157,20.701 -186.157,42.729

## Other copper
Layer 1:
  region net SGND: -23.596,20.751 -21.082,18.237 -21.082,20.345 -20.421,21.006
  region net SGND: -97.053,17.17 -96.444,17.17 -91.923,21.692 -92.532,22.301 -97.333,22.301
Layer 2:
  region net SGND: -23.498,20.653 -20.835,17.99 -20.835,21.009 -20.545,21.3
  region net SGND: -96.051,17.563 -92.888,20.726 -96.215,20.726 -96.393,20.904
Layer 4:
  region net SGND: -24.936,22.092 -19.507,16.662 -19.507,21.3 -18.442,22.365
  region net SGND: -97.053,17.17 -96.444,17.17 -91.313,22.301 -93.294,24.282 -97.104,24.282 -97.307,24.079
Bottom Layer:
  region net HVBUS: -186.385,-13.157 -180.467,-13.157 -179.883,-13.741 -179.883,-24.181 -180.81,-25.108 -186.08,-25.108 -186.728,-24.46 -186.728,-13.5

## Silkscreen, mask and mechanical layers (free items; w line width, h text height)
M1 Board Outline:
  lines w0.025: -187.046,-80.289 -187.02,52.324 64.999,52.273 ; -187.02,-80.289 65.024,-80.289 65.024,52.324
M9 Title Sheet:
  drawing of 52 lines, arcs and shapes, not listed
  text "1" at -152.912,117.437 h1.78
  text "2" at -89.522,117.437 h1.78
  text "3" at -26.293,117.437 h1.78
  text "4" at 37.376,117.437 h1.78
  text "5" at 100.851,117.437 h1.78
  text "6" at 164.478,117.437 h1.78
  text "A" at -182.283,88.405 h1.78
  text "A" at 193.637,88.405 h1.78
  text "B" at 193.637,27.953 h1.78
  text "C" at 193.637,-32.372 h1.78
  text "PROJECT TITLE:" at 116.421,-79.642 h1.14
  text ".PRJ_Title" at 117.691,-83.028 h1.78
  text "DESIGNED FOR:" at 116.421,-87.287 h1.14
  text ".PRJ_Customer" at 117.691,-90.843 h1.78
  text "D" at -182.283,-92.57 h1.78
  text "D" at 193.637,-92.57 h1.78
  text "FILE NAME:" at 116.421,-94.907 h1.14
  text ".PCB_File_Name_No_Path" at 117.691,-97.955 h1.78
  text "Texas Instruments (TI) and/or its licensors do not warrant the accuracy or completeness of this specification" at -9.804,-102.066 h1.14
  text "ENGINEER:" at 116.421,-102.273 h1.14
  text "LAYOUT BY:" at 154.648,-102.273 h1.14
  text "or any information contained therein. TI and/or its licensors do not warrant that this design will meet" at -10.947,-104.927 h1.14
  text ".PRJ_Engineer" at 117.691,-106.21 h1.78
  text ".PCB_Layout" at 155.931,-106.21 h1.78
  text "the specifications, will be suitable for your application or fit for any particular purpose, or will operate in" at -10.947,-107.789 h1.14
  text "ALTIUM DESIGNER VERSION:" at 154.648,-110.147 h1.14
  text "an implementation. TI and/or its licensors do not warrant that the design is production worthy. You should" at -10.947,-110.651 h1.14
  text "completely validate and test your design implementation to confirm the system functionality for your application." at -9.804,-113.513 h1.14
  text ".print_Scale" at 117.691,-113.534 h1.78
  text ".Application_BuildNumber" at 155.931,-113.534 h1.78
  text "1" at -152.912,-118.783 h1.78
  text "2" at -89.522,-118.783 h1.78
  text "3" at -26.293,-118.783 h1.78
  text "4" at 37.376,-118.783 h1.78
  text "5" at 100.851,-118.783 h1.78
  text "6" at 164.478,-118.783 h1.78
M17 Embedded Cavity:
  text ".Layer_Name" at -157.048,-108.496 h1.52
M18 Embedded Assembly:
  text ".Layer_Name" at -157.048,-108.496 h1.52
M19 Embedded Keepout:
  text ".Layer_Name" at -157.048,-108.496 h1.52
